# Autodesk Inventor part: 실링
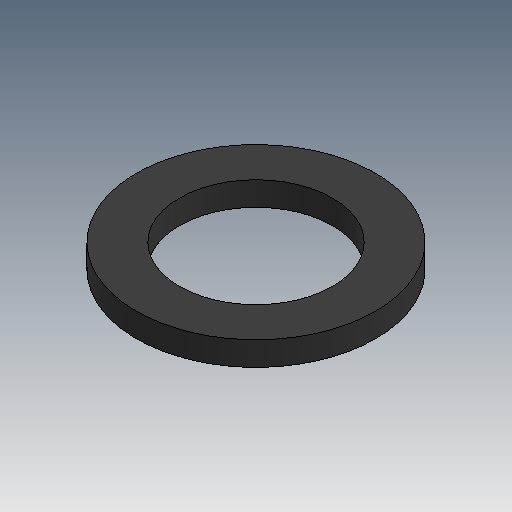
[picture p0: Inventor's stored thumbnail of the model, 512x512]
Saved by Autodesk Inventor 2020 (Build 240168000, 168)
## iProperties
Created: 2024-11
Part Number: 실링
Material: 고무
Document SubType Name: Modeling
Designer: shin
Density: 0.93 g/cm^3
Appearance: 기본값
Author: jhkim
Sending System: Autodesk Inventor 2025
Preprocessor: ST-DEVELOPER v20
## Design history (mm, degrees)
feature "솔리드1"
node "솔리드2"
